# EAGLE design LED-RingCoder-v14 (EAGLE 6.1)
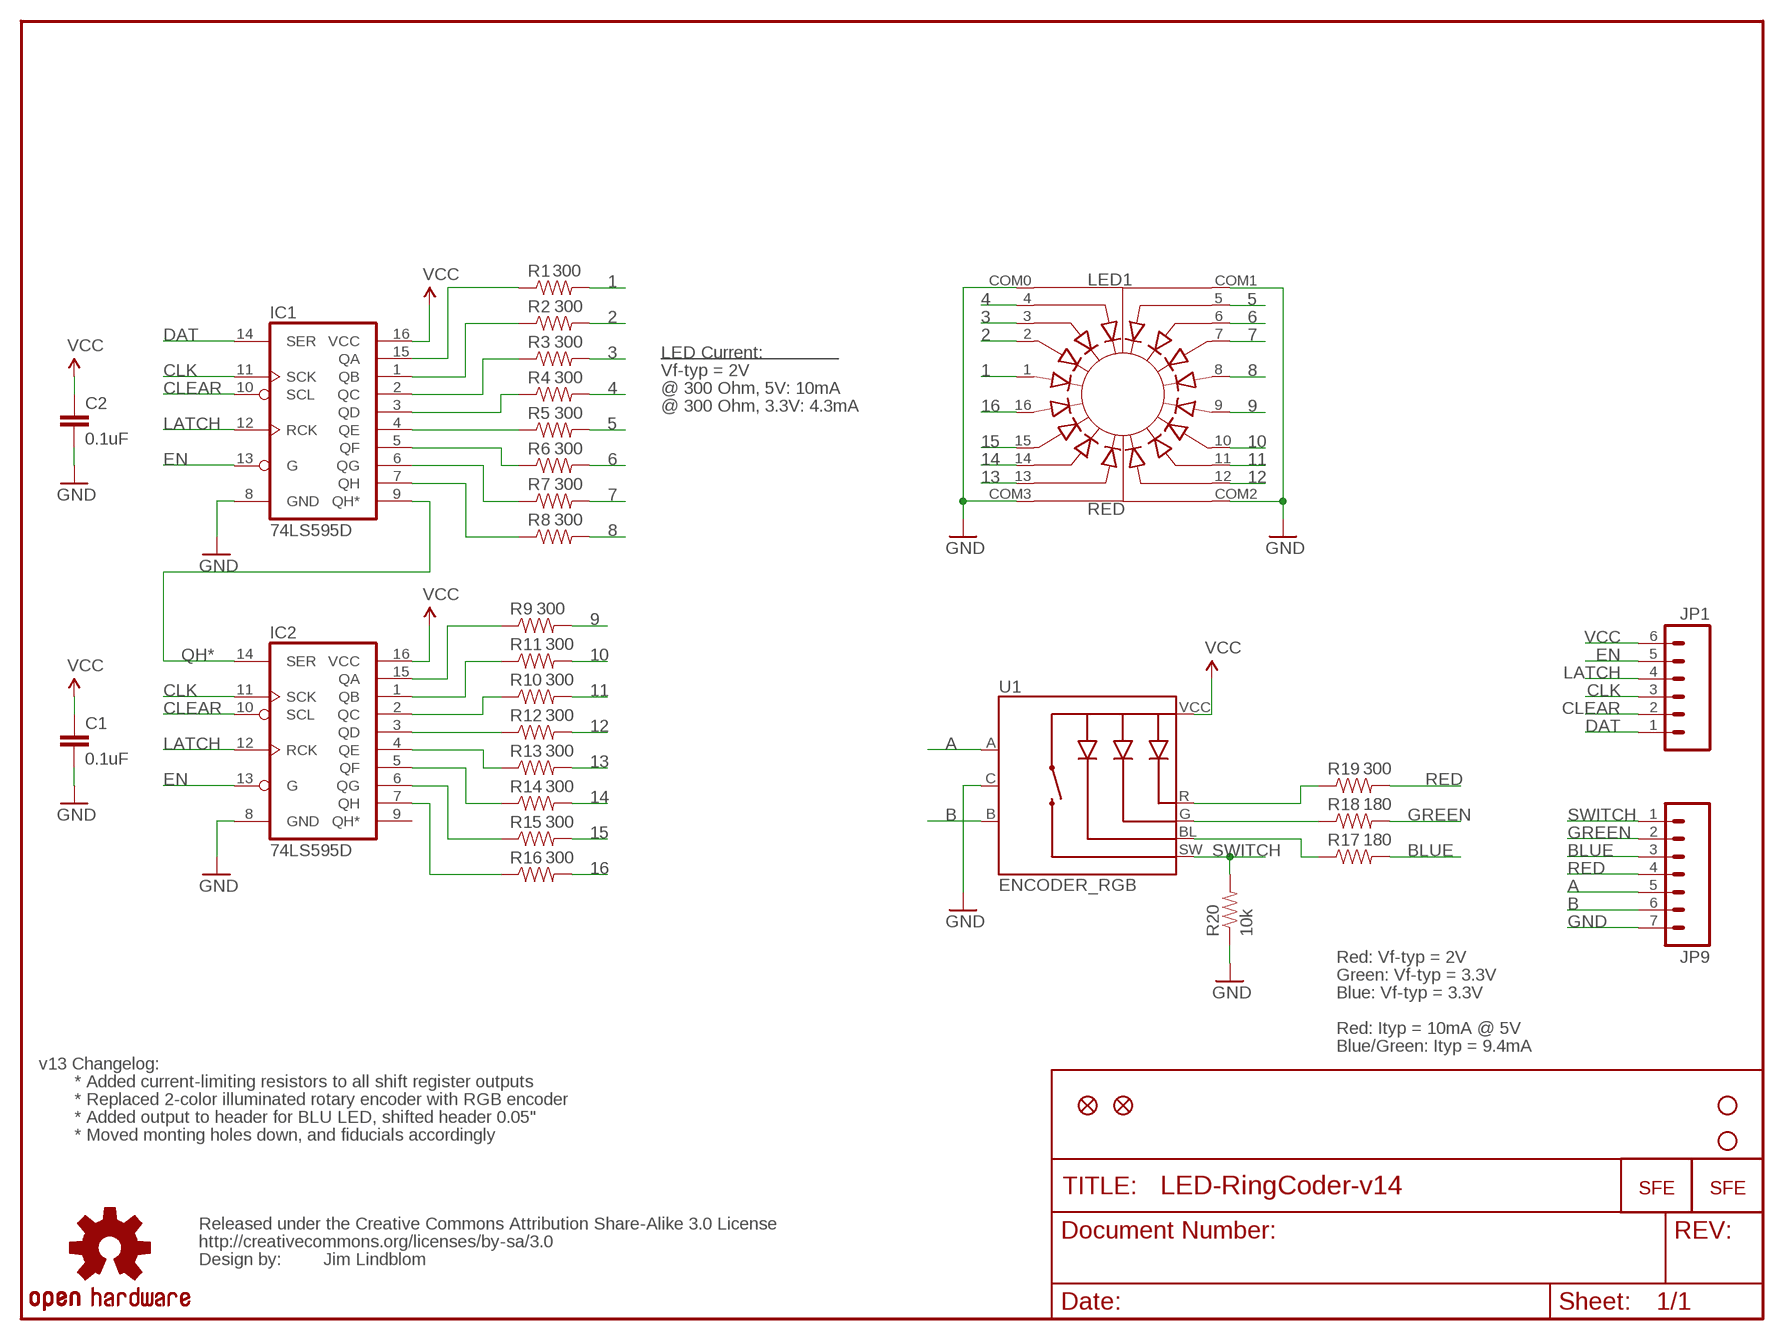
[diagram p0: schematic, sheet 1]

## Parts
C1  0.1uF  CAP0402-CAP  [0402-CAP]
C2  0.1uF  CAP0402-CAP  [0402-CAP]
IC1  74LS595D  [SO16]
IC2  74LS595D  [SO16]
JP1  M06SIP  [1X06]
JP2  LOGO-SFENW2  [SFE-NEW-WEB]
JP3  STAND-OFF  [STAND-OFF]
JP4  STAND-OFF  [STAND-OFF]
JP5  FIDUCIAL1X2.5  [FIDUCIAL-1X2.5]
JP6  LOGO-SFESK  [SFE-LOGO-FLAME]
JP8  FIDUCIAL1X2.5  [FIDUCIAL-1X2.5]
JP9  M07  [1X07]
LED1  RED  LED_RING  [LED_RING]
R1  300  RESISTOR0402-RES  [0402-RES]
R2  300  RESISTOR0402-RES  [0402-RES]
R3  300  RESISTOR0402-RES  [0402-RES]
R4  300  RESISTOR0402-RES  [0402-RES]
R5  300  RESISTOR0402-RES  [0402-RES]
R6  300  RESISTOR0402-RES  [0402-RES]
R7  300  RESISTOR0402-RES  [0402-RES]
R8  300  RESISTOR0402-RES  [0402-RES]
R9  300  RESISTOR0402-RES  [0402-RES]
R10  300  RESISTOR0402-RES  [0402-RES]
R11  300  RESISTOR0402-RES  [0402-RES]
R12  300  RESISTOR0402-RES  [0402-RES]
R13  300  RESISTOR0402-RES  [0402-RES]
R14  300  RESISTOR0402-RES  [0402-RES]
R15  300  RESISTOR0402-RES  [0402-RES]
R16  300  RESISTOR0402-RES  [0402-RES]
R17  180  RESISTOR0402-RES  [0402-RES]
R18  180  RESISTOR0402-RES  [0402-RES]
R19  300  RESISTOR0402-RES  [0402-RES]
R20  10k  RESISTOR0402-RES  [0402-RES]
U1  ENCODER_RGB  [ENCODER_LED_RGB]
U$1  CREATIVE_COMMONS  [CREATIVE_COMMONS]
U$2  OSHW-LOGOS  [OSHW-LOGO-S]

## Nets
1: LED1.1 R1.2
2: LED1.2 R2.2
3: LED1.3 R3.2
4: LED1.4 R4.2
5: LED1.5 R5.2
6: LED1.6 R6.2
7: LED1.7 R7.2
8: LED1.8 R8.2
9: LED1.9 R9.2
10: LED1.10 R11.2
11: LED1.11 R10.2
12: LED1.12 R12.2
13: LED1.13 R13.2
14: LED1.14 R14.2
15: LED1.15 R15.2
16: LED1.16 R16.2
A: JP9.5 U1.A
B: JP9.6 U1.B
BLUE: JP9.3 R17.2
CLEAR: IC1.10(SCL) IC2.10(SCL) JP1.2
CLK: IC1.11(SCK) IC2.11(SCK) JP1.3
DAT: IC1.14(SER) JP1.1
EN: IC1.13(G) IC2.13(G) JP1.5
GND: C1.2 C2.2 IC1.8(GND) IC2.8(GND) JP9.7 LED1.COM0 LED1.COM1 LED1.COM2 LED1.COM3 R20.1 U1.C
GREEN: JP9.2 R18.2
LATCH: IC1.12(RCK) IC2.12(RCK) JP1.4
LED-B: R17.1 U1.BL
LED-G: R18.1 U1.G
LED-R: R19.1 U1.R
N$1: IC1.15(QA) R1.1
N$2: IC1.1(QB) R2.1
N$3: IC1.2(QC) R3.1
N$4: IC1.3(QD) R4.1
N$5: IC1.4(QE) R5.1
N$6: IC1.5(QF) R6.1
N$7: IC1.6(QG) R7.1
N$8: IC1.7(QH) R8.1
N$9: IC2.15(QA) R9.1
N$10: IC2.1(QB) R11.1
N$11: IC2.2(QC) R10.1
N$12: IC2.3(QD) R12.1
N$13: IC2.4(QE) R13.1
N$14: IC2.5(QF) R14.1
N$15: IC2.6(QG) R15.1
N$16: IC2.7(QH) R16.1
QH*: IC1.9(QH*) IC2.14(SER)
RED: JP9.4 R19.2
SWITCH: JP9.1 R20.2 U1.SW
VCC: C1.1 C2.1 IC1.16(VCC) IC2.16(VCC) JP1.6 U1.VCC
Unconnected: IC2.9(QH*)

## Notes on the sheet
- LED Current:
- Vf-typ = 2V
- @ 300 Ohm, 5V: 10mA
- @ 300 Ohm, 3.3V: 4.3mA
- Red: Vf-typ = 2V
- Green: Vf-typ = 3.3V
- Blue: Vf-typ = 3.3V
- Red: Ityp = 10mA @ 5V
- Blue/Green: Ityp = 9.4mA
- v13 Changelog:
- * Added current-limiting resistors to all shift register outputs
- * Replaced 2-color illuminated rotary encoder with RGB encoder
- * Added output to header for BLU LED, shifted header 0.05"
- * Moved monting holes down, and fiducials accordingly
- Jim Lindblom

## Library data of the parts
C1 C2 = SparkFun:CAP: Capacitor
IC1 IC2 = SparkFun:74*595: 8-bit SHIFT REGISTER, output latch
JP1 = SparkFun:M06: Header 6 Standard 6-pin 0.1" header. Use with straight break away headers (SKU : PRT-00116), right angle break away headers (PRT-00553), swiss pins (PRT-00743), machine pins (PRT-00117), and female headers (PRT-00115). Molex polarized connector foot print use with SKU : PRT-08094 with associated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
JP2 JP6 = SparkFun:LOGO-SFE: Spark Fun Electronics PCB Logo
JP3 JP4 = SparkFun:STAND-OFF: Stand Off
JP5 JP8 = abes:FIDUCIAL: Fiducial Alignment Points
JP9 = SparkFun:M07: Header 7 Standard 7-pin 0.1" header. Use with straight break away headers (SKU : PRT-00116), right angle break away headers (PRT-00553), swiss pins (PRT-00743), machine pins (PRT-00117), and female headers (PRT-00115). NOTES ON THE VARIANTS LOCK and LOCK_LONGPADS... This footprint was designed to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
LED1 = SparkFun:LED_RING: 16 LED Ring http://dlnmh9ip6v2uc.cloudfront.net/datasheets/Components/LED/Top-Up%20LED%20Ring%20LED-CCL-A.pdf
R1-R20 = SparkFun:RESISTOR: Resistor
U1 = SparkFun:ENCODER_RGB: Illuminated Rotary Encoder w/ RGB LED and select switch EC12PLRGBSDVBF-D: http://top-up.so-buy.com/front/bin/ptdetail.phtml?Part=EC12PLRGBSDVBF-D
U$1 = SparkFun:CREATIVE_COMMONS
U$2 = SparkFun:OSHW-LOGO: Open Source Hardware Logo This logo indicates the piece of hardware it is found on incorporates a OSHW license and/or adheres to the definition of open source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

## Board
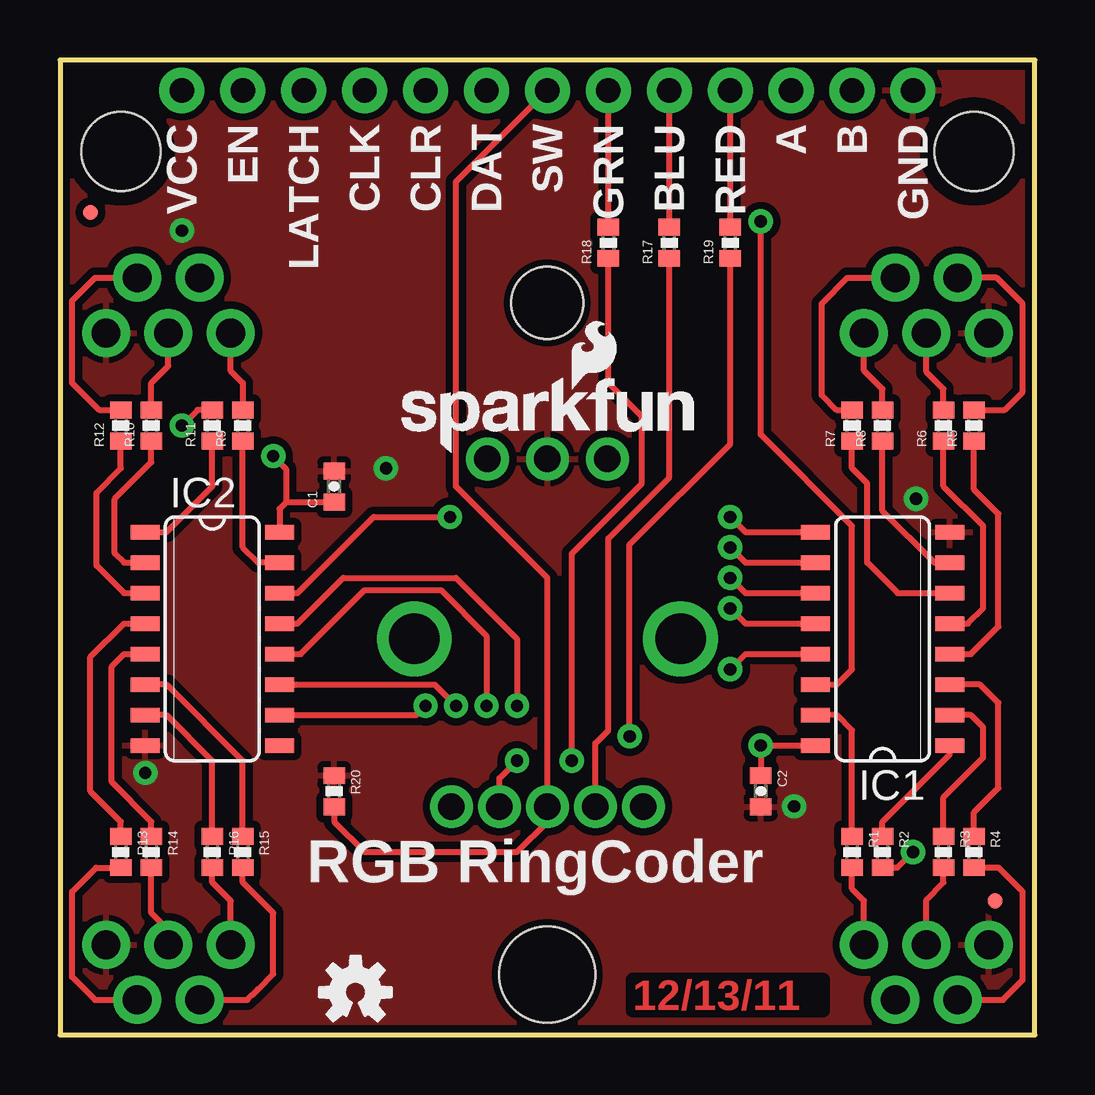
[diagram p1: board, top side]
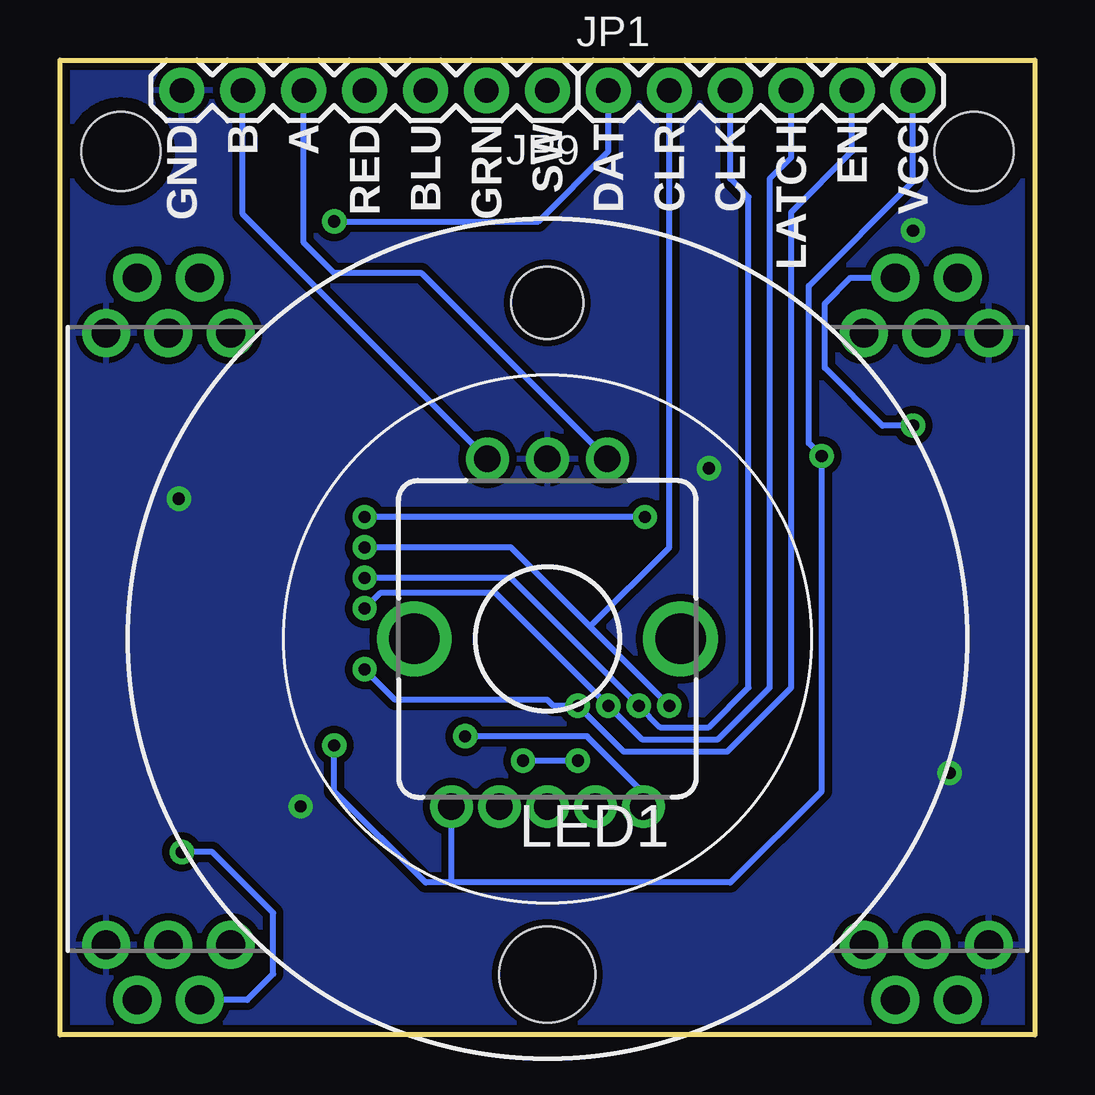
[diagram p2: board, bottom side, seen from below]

Size 40.64 x 40.64 mm. Coordinates in mm from the lower left corner, seen from the top.
Outline: 40.64,0 40.64,40.64 0,40.64 0,0 40.64,0
Copper layers (1*16): Top 0.035mm / dielectric 1.5mm / Bottom 0.035mm
Design rules "SparkFun *": minimum track width 8mil, minimum drill 20mil, track to track 8mil, track to pad 8mil, pad to pad 8mil, via to via 8mil, smd to smd 8mil, copper to edge 8mil, drill to drill 8mil, minimum pad ring 12mil, minimum via ring 10mil, stop-mask expansion 4mil, vias tented up to drill 20mil, thermal gap 10mil

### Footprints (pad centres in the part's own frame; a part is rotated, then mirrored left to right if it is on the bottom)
0402-CAP = smd 0.7 x 0.9: 1 -0.65,0; 2 0.65,0
SO16 = smd 0.6 x 1.2: 1 -4.445,-2.8; 2 -3.175,-2.8; 3 -1.905,-2.8; 4 -0.635,-2.8; 5 0.635,-2.8; 6 1.905,-2.8; 7 3.175,-2.8; 8 4.445,-2.8; 9 4.445,2.8; 10 3.175,2.8; 11 1.905,2.8; 12 0.635,2.8; 13 -0.635,2.8; 14 -1.905,2.8; 15 -3.175,2.8; 16 -4.445,2.8
1X06 = drill 1.016 pad 1.88 round: 1 0,0; 2 2.54,0; 3 5.08,0; 4 7.62,0; 5 10.16,0; 6 12.7,0
STAND-OFF = hole 3.302: 0,0
FIDUCIAL-1X2.5 = smd 0.635 x 0.635: 1 0,0
1X07 = drill 1.016 pad 1.88 round: 1 0,0; 2 2.54,0; 3 5.08,0; 4 7.62,0; 5 10.16,0; 6 12.7,0; 7 15.24,0
LED_RING = drill 1.2 pad 2 round: 1 13.2,12.75; 2 14.5,15.05; 3 15.8,12.75; 4 17.1,15.05; 5 17.1,-15.05; 6 15.8,-12.75; 7 14.5,-15.05; 8 13.2,-12.75; 9 -13.2,-12.75; 10 -14.5,-15.05; 11 -15.8,-12.75; 12 -17.1,-15.05; 13 -17.1,15.05; 14 -15.8,12.75; 15 -14.5,15.05; 16 -13.2,12.75; COM0 18.4,12.75; COM1 18.4,-12.75; COM2 -18.4,-12.75; COM3 -18.4,12.75 | hole 4: 0,14 | hole 3: 0,-14
0402-RES = smd 0.7 x 0.9: 1 -0.65,0; 2 0.65,0
ENCODER_LED_RGB = drill 1.1 pad 1.8 round: A -2.5,-7.5; B 2.5,-7.5; C 0,-7.5 | drill 1.1 pad 1.778 round: BL 2,7; G -2,7; R -4,7; SW 0,7; VCC 4,7 | drill 2.1 round: P$1 -5.55,0; P$2 5.55,0

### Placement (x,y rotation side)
C1  11.43,22.86 90 top
C2  29.21,10.16 270 top
IC1  34.29,16.51 90 top
IC2  6.35,16.51 270 top
JP1  17.78,39.37 0 bottom
JP2  14.22,24.26 0 top
JP3  38.1,36.83 0 bottom
JP4  2.54,36.83 0 bottom
JP5  38.99,5.59 0 top
JP6  21.34,26.92 0 top
JP8  1.27,34.29 0 top
JP9  20.32,39.37 180 bottom
LED1  20.32,16.51 180 bottom
R1  33.02,7.62 270 top
R2  34.29,7.62 270 top
R3  36.83,7.62 270 top
R4  38.1,7.62 270 top
R5  38.1,25.4 90 top
R6  36.83,25.4 90 top
R7  33.02,25.4 90 top
R8  34.29,25.4 90 top
R9  7.62,25.4 90 top
R10  3.81,25.4 90 top
R11  6.35,25.4 90 top
R12  2.54,25.4 90 top
R13  2.54,7.62 270 top
R14  3.81,7.62 270 top
R15  7.62,7.62 270 top
R16  6.35,7.62 270 top
R17  25.4,33.02 90 top
R18  22.86,33.02 90 top
R19  27.94,33.02 90 top
R20  11.43,10.16 270 top
U1  20.32,16.51 180 bottom
U$1  not placed on the board
U$2  12.32,1.78 0 top

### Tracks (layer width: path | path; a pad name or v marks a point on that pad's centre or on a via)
1
  Top 0.254: R1.2 33.02,6.1 33.52,5.6 LED1.1
2  (via drill 0.51)
  Top 0.254: R2.2 34.91,6.97 v35.56,7.62
  Bottom 0.254: LED1.2 32.83,1.46 31.75,2.54 31.75,5.08 34.29,7.62 v35.56,7.62
3
  Top 0.254: R3.2 36.83,6.35 36.12,5.64 LED1.3
4
  Top 0.254: R4.2 39.13,6.97 40.13,5.97 40.13,2.29 39.31,1.46 LED1.4
5
  Top 0.254: R5.2 39.38,26.05 40.13,26.8 40.13,30.48 39.05,31.56 LED1.5
6
  Top 0.254: R6.2 36.83,26.92 36.12,27.63 LED1.6
7
  Top 0.254: R7.2 32.37,26.05 31.75,26.67 31.75,30.48 32.83,31.56 LED1.7
8
  Top 0.254: R8.2 34.29,26.92 33.52,27.69 LED1.8
9
  Top 0.254: R9.2 7.62,27.18 7.12,27.68 LED1.9
10  (via drill 0.51)
  Top 0.254: R11.2 5.73,26.05 v5.08,25.4
  Bottom 0.254: LED1.10 7.68,31.56 8.76,30.48 8.76,27.81 6.35,25.4 v5.08,25.4
11
  Top 0.254: R10.2 3.81,27.18 4.52,27.89 LED1.11
12
  Top 0.254: R12.2 1.64,26.05 0.51,27.18 0.51,30.61 1.46,31.56 LED1.12
13
  Top 0.254: R13.2 1.51,6.97 0.51,5.97 0.51,2.41 1.46,1.46 LED1.13
14
  Top 0.254: LED1.14 4.52,4.37 3.81,5.08 R14.2
15
  Top 0.254: R15.2 7.62,6.35 8.89,5.08 8.89,2.54 8.26,1.91 | 8.26,1.91 8,1.65 | LED1.15 7.81,1.46 8.26,1.91
16
  Top 0.254: LED1.16 7.12,5.58 6.35,6.35 R16.2
A
  Bottom 0.254: JP9.5 30.48,33.02 29.21,31.75 25.56,31.75 U1.A
B
  Bottom 0.254: JP9.6 33.02,34.21 U1.B
BLUE
  Top 0.254: R17.2 JP9.3
CLEAR  (via drill 0.51)
  Top 0.254: IC1.10 28.57,19.68 v27.94,20.32 | IC2.10 14.86,13.34 v15.24,13.72
  Bottom 0.254: v15.24,13.72 18.54,17.02 | 18.54,17.02 21.84,20.32 v27.94,20.32 | JP1.2 15.24,20.32 18.54,17.02
CLK  (via drill 0.51)
  Top 0.254: IC1.11 28.57,18.41 v27.94,19.05 | IC2.11 15.62,14.61 v16.51,13.72
  Bottom 0.254: JP1.3 12.7,35.69 11.94,34.92 11.94,14.48 13.59,12.83 15.62,12.83 v16.51,13.72 21.84,19.05 v27.94,19.05
DAT  (via drill 0.51)
  Top 0.254: IC1.14 32.38,14.61 33.02,15.24 33.02,21.21 29.21,25.02 v29.21,33.91
  Bottom 0.254: v29.21,33.91 20.7,33.91 17.78,36.83 JP1.1
EN  (via drill 0.51)
  Top 0.254: IC1.13 28.57,15.88 v27.94,15.24 | IC2.13 9.91,17.14 11.81,19.05 16.51,19.05 19.05,16.51 v19.05,13.72
  Bottom 0.254: v27.94,15.24 26.67,13.97 20.32,13.97 20.07,13.72 v19.05,13.72 17.14,11.81 12.83,11.81 10.16,14.48 10.16,34.29 7.62,36.83 JP1.5
GND  (via drill 0.51)
  other vias: 35.69,22.35 3.56,10.92 30.61,9.53 13.59,23.62 5.08,33.53
  pour Top (isolate 0.305): 40.64,0 40.64,40.64 0,40.64 0,0
  pour Bottom (isolate 0.305): 40.64,0 40.64,40.64 0,40.64 0,0
GREEN
  Top 0.254: R18.2 JP9.2
LATCH  (via drill 0.51)
  Top 0.254: IC1.12 28.57,17.14 v27.94,17.78 | IC2.12 10.03,15.88 12.7,18.54 15.88,18.54 17.78,16.64 v17.78,13.72
  Bottom 0.254: v27.94,17.78 27.3,18.41 22.48,18.41 v17.78,13.72 16.38,12.32 13.21,12.32 11.05,14.48 11.05,35.69 10.16,36.58 JP1.4
LED-B
  Top 0.254: R17.1 25.4,23.24 22.86,20.7 22.86,12.7 22.32,12.16 U1.BL
LED-G  (via drill 0.51)
  Top 0.254: v19.05,11.43 18.32,10.7 U1.G | v21.34,11.43 21.34,20.07 24.26,22.99 24.26,25.78 22.86,27.18 R18.1
  Bottom 0.254: v19.05,11.43 v21.34,11.43
LED-R  (via drill 0.51)
  Top 0.254: v23.75,12.45 23.75,20.45 27.94,24.64 R19.1
  Bottom 0.254: v23.75,12.45 18.67,12.45 16.32,10.1 U1.R
N$1
  Top 0.254: IC1.15 32.38,13.34 33.02,12.7 R1.1
N$2
  Top 0.254: R2.1 34.29,8.89 37.09,11.69 IC1.1
N$3
  Top 0.254: IC1.2 37.97,13.34 38.48,12.83 38.48,11.56 36.83,9.91 R3.1
N$4
  Top 0.254: IC1.3 38.35,14.61 39.12,13.84 39.12,10.29 38.1,9.27 R4.1
N$5
  Top 0.254: IC1.4 37.97,15.88 39.12,17.02 39.12,21.72 38.1,22.73 R5.1
N$6
  Top 0.254: IC1.5 37.85,17.14 38.48,17.78 38.48,21.21 36.83,22.86 R6.1
N$7
  Top 0.254: IC1.6 34.92,18.41 33.66,19.68 33.66,22.99 33.02,23.62 R7.1
N$8
  Top 0.254: IC1.7 36.45,19.68 34.29,21.84 R8.1
N$9
  Top 0.254: R9.1 7.62,20.32 8.26,19.68 IC2.15
N$10
  Top 0.254: IC2.1 4.45,20.95 6.35,22.86 R11.1
N$11
  Top 0.254: R10.1 3.81,23.88 2.29,22.35 2.29,20.07 2.67,19.68 IC2.2
N$12
  Top 0.254: IC2.3 2.67,18.41 1.52,19.56 1.52,22.61 2.54,23.62 R12.1
N$13
  Top 0.254: R13.1 2.54,8.89 1.27,10.16 1.27,15.75 2.67,17.14 IC2.4
N$14
  Top 0.254: R14.1 3.81,8.89 2.16,10.54 2.16,15.37 2.67,15.88 IC2.5
N$15
  Top 0.254: R15.1 7.62,11.43 4.45,14.61 IC2.6
N$16
  Top 0.254: IC2.7 4.45,13.34 6.35,11.43 R16.1
QH*  (via drill 0.51)
  Top 0.254: IC1.9 28.57,20.95 v27.94,21.59 | IC2.14 9.91,18.41 13.08,21.59 v16.26,21.59
  Bottom 0.254: v16.26,21.59 v27.94,21.59
RED
  Top 0.254: R19.2 JP9.4
SWITCH
  Top 0.254: JP9.1 16.51,35.56 16.51,22.86 20.32,19.05 U1.SW 20.32,8.89 19.05,7.62 12.7,7.62 11.43,8.89 R20.2
VCC  (via drill 0.51)
  Top 0.254: IC1.16 v29.21,12.06 C2.1 | 9.44,22.21 C1.1 | 9.44,22.21 9.42,22.23 9.42,23.6 v8.89,24.13 | IC2.16 9.15,21.92 9.44,22.21
  Bottom 0.254: JP1.6 5.08,35.56 9.42,31.22 9.42,24.66 v8.89,24.13 8.89,10.16 12.7,6.35 24.38,6.35 | v29.21,12.06 29.21,10.16 25.4,6.35 24.38,6.35 | U1.VCC 24.32,6.41 24.38,6.35

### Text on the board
Top: 12/13/11
tPlace: VCC | EN | LATCH | CLK | CLR | DAT | SW | GRN | BLU | RED | A | B | GND | RGB RingCoder
bPlace: VCC | EN | LATCH | CLK | CLR | DAT | SW | GRN | BLU | RED | A | B | GND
